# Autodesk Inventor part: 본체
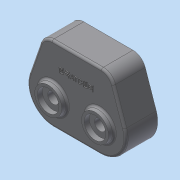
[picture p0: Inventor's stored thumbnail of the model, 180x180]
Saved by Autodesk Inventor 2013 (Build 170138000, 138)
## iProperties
Created: 2014-12
Part Number: 본체
Material: 일반
Document SubType Name: Modeling
Designer: dgall
Density: 1 g/cm^3
Author: dgall
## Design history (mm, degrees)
sketch "스케치1"
  geometry: L1 (0, 0)-(0, 36.035); L2 (0, 0)-(0, -46); L3 (0, 0)-(-32.527, -32.527); L4 (0, 0)-(32.527, -32.527); L5 (47, 36)-(-47, 36); L6 (-47, 36)-(-66.565, -20.803); L7 (47, 36)-(67.678, -24.037); L8 (-32.527, -68.527)-(32.527, -68.527); A1 r 46 centre (0, 0) between (-28.636, 36) and (28.636, 36); A2 r 36 centre (-32.527, -32.527) between (-66.565, -20.803) and (-32.527, -68.527); A3 r 36 centre (32.527, -32.527) between (32.527, -68.527) and (66.565, -20.803); 2 further points
  constraints: 16 end point, 9 point on circle, 3 centre point, 3 coincident, 3 point on line, 3 tangent, 1 collinear, 1 midpoint, 1 parallel, 1 perpendicular, 1 vertical, 1 vertical alignment
  dimensions: "d0" = 46 radius of A1; "d4" = 45 deg angle of L2 L3; "d6" = 45 deg angle of L4 L2; "d8" = 36 radius of A2; "d9" = 94 distance of L5.start L5.end; "d10" = 36 distance from line of L5 point (0, 0); "d11" = 36 radius of A3
extrude "돌출1" new body sketch "스케치1" distance "d12" = 44; taper "d13" = 0 deg
sketch "스케치2"
  geometry: L1 (-47, 36)-(47, 36) reference; L2 (-66.565, -20.803)-(-47, 36) reference; L3 (32.527, -68.527)-(-32.527, -68.527) reference; L4 (47, 36)-(66.565, -20.803) reference; L5 (43.434, 31)-(-43.434, 31); L6 (-43.434, 31)-(-61.837, -22.432); L7 (-32.527, -63.527)-(32.527, -63.527); L8 (61.837, -22.432)-(43.434, 31); A1 r 36 centre (-32.527, -32.527) between (-66.565, -20.803) and (-32.527, -68.527) reference; A2 r 36 centre (32.527, -32.527) between (32.527, -68.527) and (66.565, -20.803) reference; A3 r 31 centre (-32.527, -32.527) between (-61.837, -22.432) and (-32.527, -63.527); A4 r 31 centre (32.527, -32.527) between (32.527, -63.527) and (61.837, -22.432); 1 further point
  constraints: 8 end point, 4 point on circle, 2 centre point, 5 other
  dimensions: "d14" = 5 distance between parallel lines of L1 L5
extrude "돌출2" cut sketch "스케치2" distance "d15" = 34; taper "d16" = 0 deg
sketch "스케치3"
  geometry: A1 r 31 centre (-32.527, -32.527) between (-61.837, -22.432) and (-32.527, -63.527) reference; A2 r 31 centre (32.527, -32.527) between (32.527, -63.527) and (61.837, -22.432) reference; A3 r 24 centre (-32.527, -32.527) between (-26.959, -9.182) and (-9.182, -26.959); A4 r 24 centre (32.527, -32.527) between (9.182, -26.959) and (26.959, -9.182); A5 r 3 centre (-26.263, -6.263) between (-26.959, -9.182) and (-23.345, -5.568); A6 r 3 centre (26.263, -6.263) between (23.345, -5.568) and (26.959, -9.182); A7 r 3 centre (-6.263, -26.263) between (-5.568, -23.345) and (-9.182, -26.959); A8 r 3 centre (6.263, -26.263) between (9.182, -26.959) and (5.568, -23.345); A9 r 24 centre (0, 0) between (-5.568, -23.345) and (5.568, -23.345); A10 r 24 centre (0, 0) between (23.345, -5.568) and (-23.345, -5.568); 1 further point
  constraints: 16 point on circle, 8 centre point, 8 tangent, 3 coincident
  dimensions: "d19" = 48 diameter of A4; "d20" = 48 diameter of A3; "d21" = 3 radius of A5; "d22" = 3 radius of A8; "d23" = 3 radius of A7; "d24" = 3 radius of A6; "d25" = 24 radius of A10; "d26" = 24 radius of A9
extrude "돌출3" join sketch "스케치3" distance "d27" = 11; taper "d28" = 0 deg
hole "구멍1" diameter "d31" = 40; stored, may be unused: countersink angle "d35" = 90 deg, drill point angle "d37" = 0 deg; dims "d29" = 10, "d30" = 10, "d32" = 6, "d33" = 4, "d34" = 2, "d36" = 12
hole "구멍2" diameter "d40" = 20; stored, may be unused: countersink angle "d44" = 90 deg, drill point angle "d46" = 0 deg; dims "d38" = 10, "d39" = 10, "d41" = 6, "d42" = 4, "d43" = 2, "d45" = 3
hole "구멍3" diameter "d49" = 15.5; stored, may be unused: countersink angle "d53" = 90 deg, drill point angle "d55" = 0 deg; dims "d47" = 10, "d48" = 10, "d50" = 6, "d51" = 35, "d52" = 11, "d54" = 21
hole "구멍4" diameter "d58" = 15.5; stored, may be unused: countersink angle "d62" = 90 deg, drill point angle "d64" = 0 deg; dims "d56" = 10, "d57" = 10, "d59" = 6, "d60" = 35, "d61" = 11, "d63" = 21
sketch "스케치4"
  geometry: C1 r 7.75 at (-32.527, 32.527) reference; C2 r 7.75 at (32.527, 32.527) reference; C3 r 20 at (-32.527, 32.527); C4 r 20 at (32.527, 32.527); A1 r 36 centre (32.527, 32.527) between (66.565, 20.803) and (32.527, 68.527) reference; A2 r 36 centre (-32.527, 32.527) between (-32.527, 68.527) and (-66.565, 20.803) reference; 1 further point
  constraints: 2 centre point, 2 coincident, 1 equal radius
  dimensions: "d65" = 40 diameter of C4
extrude "돌출4" join sketch "스케치4" distance "d67" = 7; taper "d68" = 0 deg
hole "구멍5" diameter "d71" = 30; stored, may be unused: countersink angle "d75" = 90 deg, drill point angle "d77" = 0 deg; dims "d69" = 10, "d70" = 10, "d72" = 6, "d73" = 10, "d74" = 11, "d76" = 7
hole "구멍6" diameter "d80" = 30; stored, may be unused: countersink angle "d84" = 90 deg, drill point angle "d86" = 0 deg; dims "d78" = 10, "d79" = 10, "d81" = 6, "d82" = 10, "d83" = 11, "d85" = 7
sketch "스케치5"
  geometry: L1 (-47, -36)-(47, -36) reference; 2 further points
  constraints: 1 vertical alignment, 1 other
  dimensions: "d87" = 30 distance from line of point (0, -6) L1
extrude "돌출5" join sketch "스케치5" distance "d88" = 1; taper "d89" = 0 deg
node "작업 평면1"
  node "작업축1"
sketch "스케치6"
  geometry: L1 (3.5, 15)-(3.5, -15) reference; L2 (-3.5, -7.75)-(-3.5, 7.75) reference; L3 (-3.5, 0)-(3.5, 0); L4 (-3.5, -15)-(-3.5, 15) reference; L5 (-3.5, -68.527)-(-3.5, -11.723) reference; L6 (-3.5, -20)-(3.718, -20); L7 (3.718, -20)-(3.718, -18.727); L8 (3.718, -18.727)-(-3.5, -20); 1 further point
  constraints: 8 end point, 2 midpoint, 2 perpendicular, 1 point on line
  dimensions: "d91" = 40 diameter of L6 L3; "d93" = 100 deg angle of L8 L5; "d95" = 1.27278 distance of L6.end L7.end
revolve "회전1" sketch "스케치6" stored, may be unused: angle "d96" = 90 deg
node "작업 평면2"
  node "작업축2"
sketch "스케치7"
  geometry: 1 further point
node "작업 평면3"
sketch "스케치8"
  geometry: L1 (-61.837, -22.432)-(-43.434, 31) reference; L2 (43.434, 31)-(61.837, -22.432) reference; L3 (32.527, -63.527)-(-32.527, -63.527) reference; L4 (-47, 36)-(47, 36) reference; L5 (32.527, -68.527)-(-32.527, -68.527) reference; L6 (0, 36)-(0, 7); L7 (0, 7)-(51.7, 7); L8 (0, 7)-(-51.7, 7); A1 r 8 centre (51.7, 7) between (49.095, 14.564) and (54.305, -0.564); A2 r 8 centre (0, -63.527) between (8, -63.527) and (-8, -63.527); A3 r 8 centre (-51.7, 7) between (-54.305, -0.564) and (-49.095, 14.564); 1 further point
  constraints: 8 point on line, 6 end point, 6 point on circle, 3 centre point, 2 coincident, 2 equal radius, 2 midpoint, 2 perpendicular, 1 collinear
  dimensions: "d105" = 8 radius of A1; "d106" = 29 distance of L6.start L6.end
extrude "돌출6" join sketch "스케치8" distance "d107" = 34; taper "d108" = 0 deg
fillet "모깎기1" dims "d109" = 3
fillet "모깎기2" dims "d110" = 18
hole "구멍7" diameter "d113" = 4.134; stored, may be unused: countersink angle "d117" = 90 deg, drill point angle "d119" = 118 deg; dims "d111" = 10, "d112" = 10, "d114" = 20, "d115" = 10, "d116" = 11, "d118" = 23
hole "구멍8" diameter "d122" = 4.134; stored, may be unused: countersink angle "d126" = 90 deg, drill point angle "d128" = 118 deg; dims "d120" = 10, "d121" = 10, "d123" = 20, "d124" = 10, "d125" = 11, "d127" = 23
hole "구멍9" diameter "d131" = 4.134; stored, may be unused: countersink angle "d135" = 90 deg, drill point angle "d137" = 118 deg; dims "d129" = 10, "d130" = 10, "d132" = 20, "d133" = 10, "d134" = 11, "d136" = 23
node "솔리드1"
mirror "대칭1"
other parameters: "d17" = 48, "d90" = 90 deg, "d97" = 90 deg, "d98" = 0
